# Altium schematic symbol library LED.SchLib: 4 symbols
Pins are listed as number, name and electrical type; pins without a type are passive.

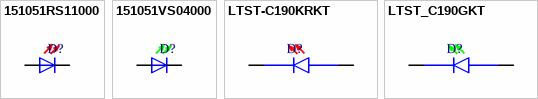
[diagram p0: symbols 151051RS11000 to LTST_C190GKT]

## 151051RS11000
designator D?  (value not drawn)
Red 645nm LED Indication - Discrete 2.1V Radial; MF: {'manufacturer': u'W\xfcrth Elektronik'}; MP: 151051VS04000
footprint 151051RS11000 (Red 645nm LED Indication - Discrete 2.1V Radial)
pins: 1 POS, 2 NEG

## 151051VS04000
designator D?  (value not drawn)
Green 572nm LED Indication - Discrete 2.1V Radial; MF: {'manufacturer': u'W\xfcrth Elektronik'}; MP: 151051VS04000
footprint 151051VS04000 (Green 572nm LED Indication - Discrete 2.1V Radial)
pins: 1 POS, 2 NEG

## LTST-C190KRKT
designator D?  (value not drawn)
Red 631nm LED Indication - Discrete 2V 0603 (1608 Metric); MF: {'manufacturer': u'Lite-On Inc.'}; MP: LTST-C190GKT
footprint LTST-C190KRKT (Red 631nm LED Indication - Discrete 2V 0603 (1608 Metric))
pins: A, C

## LTST_C190GKT
designator D?  (value not drawn)
Green 569nm LED Indication - Discrete 2.1V 0603 (1608 Metric); MF: Lite-On Inc.; MP: LTST-C190KRKT
footprint LTST-C190GKT (Green 569nm LED Indication - Discrete 2.1V 0603 (1608 Metric))
pins: A, C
